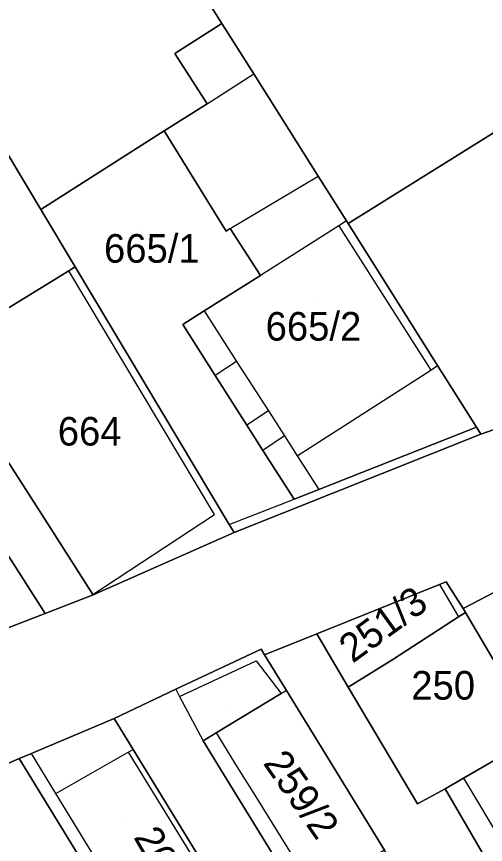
# Model space of a CAD drawing. Extents: x -263943 to -261149, y -1236934 to -1230686.
# Drawn here: x -262505 to -262472.2, y -1235556.7 to -1235498.8 of the extents above; entities that cross this region are included whole.
import ezdxf

# ---------------------------------------------------------------- set-up
doc = ezdxf.new("R2010")
doc.units = 0
for name, color, linetype in [('body_kn', 7, 'Continuous'), ('kladpar_druhypozemkov', 7, 'Continuous'), ('kladpar_hranice', 7, 'Continuous'), ('kladpar_parcelnecisla', 7, 'Continuous'), ('kladpar_plochy', 7, 'Continuous'), ('zappar_hrandruhpozemk', 7, 'Continuous')]:
    doc.layers.add(name, color=color, linetype=linetype)

msp = doc.modelspace()

# ---------------------------------------------------------------- linework, layer by layer
at = {"layer": 'body_kn'}
for p, q in [((-262490.64, -1235499.3), (-262490.64, -1235499.3)), ((-262490.64, -1235499.3), (-262490.64, -1235499.3)), ((-262493.93, -1235501.39), (-262493.93, -1235501.39)), ((-262488.41, -1235502.83), (-262488.41, -1235502.83)), ((-262491.68, -1235504.91), (-262491.68, -1235504.91)), ((-262491.68, -1235504.91), (-262491.68, -1235504.91)), ((-262494.68, -1235506.81), (-262494.68, -1235506.81)), ((-262494.68, -1235506.81), (-262494.68, -1235506.81)), ((-262483.9, -1235509.98), (-262483.9, -1235509.98)), ((-262503.31, -1235512.3), (-262503.31, -1235512.3)), ((-262481.93, -1235513.11), (-262481.93, -1235513.11)), ((-262481.93, -1235513.11), (-262481.93, -1235513.11)), ((-262490.05, -1235513.65), (-262490.05, -1235513.65)), ((-262490.05, -1235513.65), (-262490.05, -1235513.65)), ((-262482.47, -1235513.45), (-262482.47, -1235513.45)), ((-262481.81, -1235513.3), (-262481.81, -1235513.3)), ((-262490.35, -1235513.83), (-262490.35, -1235513.83)), ((-262501.34, -1235516.6), (-262501.34, -1235516.6)), ((-262501.34, -1235516.6), (-262501.34, -1235516.6)), ((-262500.9, -1235516.33), (-262500.9, -1235516.33)), ((-262487.95, -1235516.92), (-262487.95, -1235516.92)), ((-262487.95, -1235516.92), (-262487.95, -1235516.92)), ((-262491.88, -1235519.4), (-262491.88, -1235519.4)), ((-262491.88, -1235519.4), (-262491.88, -1235519.4)), ((-262493.38, -1235520.35), (-262493.38, -1235520.35)), ((-262489.61, -1235522.94), (-262489.61, -1235522.94)), ((-262489.61, -1235522.94), (-262489.61, -1235522.94)), ((-262476.03, -1235523.54), (-262476.03, -1235523.54)), ((-262476.03, -1235523.54), (-262476.03, -1235523.54)), ((-262475.55, -1235523.23), (-262475.55, -1235523.23)), ((-262491.11, -1235523.92), (-262491.11, -1235523.92)), ((-262487.39, -1235526.4), (-262487.39, -1235526.4)), ((-262487.39, -1235526.4), (-262487.39, -1235526.4)), ((-262488.9, -1235527.39), (-262488.9, -1235527.39)), ((-262472.84, -1235527.54), (-262472.84, -1235527.54)), ((-262486.27, -1235528.14), (-262486.27, -1235528.14)), ((-262486.27, -1235528.14), (-262486.27, -1235528.14)), ((-262472.53, -1235528.03), (-262472.53, -1235528.03)), ((-262487.77, -1235529.17), (-262487.77, -1235529.17)), ((-262485.38, -1235529.53), (-262485.38, -1235529.53)), ((-262483.86, -1235531.89), (-262483.86, -1235531.89)), ((-262485.59, -1235532.57), (-262485.59, -1235532.57)), ((-262491.15, -1235533.64), (-262491.15, -1235533.64)), ((-262491.15, -1235533.64), (-262491.15, -1235533.64)), ((-262490.12, -1235534.35), (-262490.12, -1235534.35)), ((-262490.12, -1235534.35), (-262490.12, -1235534.35)), ((-262502.5, -1235534.82), (-262502.5, -1235534.82)), ((-262489.79, -1235534.91), (-262489.79, -1235534.91)), ((-262489.79, -1235534.91), (-262489.79, -1235534.91)), ((-262475.43, -1235538.55), (-262475.43, -1235538.55)), ((-262475.43, -1235538.55), (-262475.43, -1235538.55)), ((-262474.96, -1235538.36), (-262474.96, -1235538.36)), ((-262499.67, -1235539.23), (-262499.67, -1235539.23)), ((-262499.67, -1235539.23), (-262499.67, -1235539.23)), ((-262499.64, -1235539.27), (-262499.64, -1235539.27)), ((-262473.77, -1235540.22), (-262473.77, -1235540.22)), ((-262502.99, -1235540.57), (-262502.99, -1235540.57)), ((-262502.99, -1235540.57), (-262502.99, -1235540.57)), ((-262474.08, -1235540.8), (-262474.08, -1235540.8)), ((-262473.61, -1235540.5), (-262473.61, -1235540.5)), ((-262483.99, -1235541.99), (-262483.99, -1235541.99)), ((-262487.9, -1235543.07), (-262487.9, -1235543.07)), ((-262487.9, -1235543.07), (-262487.9, -1235543.07)), ((-262488.25, -1235543.88), (-262488.25, -1235543.88)), ((-262487.66, -1235543.46), (-262487.66, -1235543.46)), ((-262487.66, -1235543.46), (-262487.66, -1235543.46)), ((-262478.68, -1235543.78), (-262478.68, -1235543.78)), ((-262493.86, -1235545.87), (-262493.86, -1235545.87)), ((-262493.86, -1235545.87), (-262493.86, -1235545.87)), ((-262486.49, -1235546.17), (-262486.49, -1235546.17)), ((-262486.13, -1235545.95), (-262486.13, -1235545.95)), ((-262481.81, -1235545.71), (-262481.81, -1235545.71)), ((-262481.81, -1235545.71), (-262481.81, -1235545.71)), ((-262493.6, -1235546.37), (-262493.6, -1235546.37)), ((-262498.17, -1235547.9), (-262498.17, -1235547.9)), ((-262491.04, -1235548.92), (-262491.04, -1235548.92)), ((-262491.04, -1235548.92), (-262491.04, -1235548.92)), ((-262491.96, -1235549.48), (-262491.96, -1235549.48)), ((-262503.46, -1235550.14), (-262503.46, -1235550.14)), ((-262496.84, -1235550.07), (-262496.84, -1235550.07)), ((-262504.81, -1235550.72), (-262504.81, -1235550.72)), ((-262503.96, -1235550.36), (-262503.96, -1235550.36)), ((-262497.19, -1235550.27), (-262497.19, -1235550.27)), ((-262489.56, -1235551.31), (-262489.56, -1235551.31)), ((-262490.49, -1235551.87), (-262490.49, -1235551.87)), ((-262473.74, -1235552.08), (-262473.74, -1235552.08)), ((-262473.74, -1235552.08), (-262473.74, -1235552.08)), ((-262488.46, -1235553.09), (-262488.46, -1235553.09)), ((-262475.03, -1235552.83), (-262475.03, -1235552.83)), ((-262502.25, -1235553.16), (-262502.25, -1235553.16)), ((-262489.37, -1235553.69), (-262489.37, -1235553.69)), ((-262476.95, -1235553.89), (-262476.95, -1235553.89))]:
    msp.add_line(p, q, dxfattribs=at)
at = {"layer": 'kladpar_druhypozemkov'}
for p, q in [((-262496.1, -1235513.63), (-262496.1, -1235513.63)), ((-262483.9, -1235518.63), (-262483.9, -1235518.63)), ((-262499.51, -1235526.83), (-262499.51, -1235526.83)), ((-262482.19, -1235543), (-262482.19, -1235543)), ((-262475.14, -1235544.52), (-262475.14, -1235544.52)), ((-262490.12, -1235547.37), (-262490.12, -1235547.37)), ((-262483.86, -1235552.94), (-262483.86, -1235552.94)), ((-262497.65, -1235555.24), (-262497.65, -1235555.24))]:
    msp.add_line(p, q, dxfattribs=at)
at = {"layer": 'kladpar_hranice'}
for points in [[(-262490.64, -1235499.3), (-262493.93, -1235501.39), (-262491.68, -1235504.91), (-262494.68, -1235506.81), (-262503.31, -1235512.3), (-262518.04, -1235487.66), (-262527.31, -1235472.16), (-262527.63, -1235471.62), (-262522.3, -1235468.31), (-262520.69, -1235467.38), (-262516.77, -1235473.71), (-262509.58, -1235469.21), (-262500.08, -1235484.3), (-262496.68, -1235489.7), (-262490.64, -1235499.3)], [(-262466.56, -1235503.77), (-262481.81, -1235513.3), (-262481.93, -1235513.11), (-262483.9, -1235509.98), (-262488.41, -1235502.83), (-262490.64, -1235499.3), (-262496.68, -1235489.7), (-262500.08, -1235484.3), (-262484.57, -1235474.74), (-262483.69, -1235476.16), (-262481.31, -1235480), (-262466.56, -1235503.77)], [(-262501.34, -1235516.6), (-262508.81, -1235521.16), (-262510.44, -1235522.15), (-262507.57, -1235526.91), (-262502.5, -1235534.82), (-262499.67, -1235539.23), (-262499.64, -1235539.27), (-262502.99, -1235540.57), (-262505.55, -1235536.58), (-262512.71, -1235525.4), (-262515.62, -1235520.86), (-262531.67, -1235496), (-262518.04, -1235487.66), (-262503.31, -1235512.3), (-262500.9, -1235516.33), (-262501.34, -1235516.6)], [(-262494.68, -1235506.81), (-262491.68, -1235504.91), (-262493.93, -1235501.39), (-262490.64, -1235499.3), (-262488.41, -1235502.83), (-262483.9, -1235509.98), (-262481.93, -1235513.11), (-262481.81, -1235513.3), (-262475.55, -1235523.23), (-262472.84, -1235527.54), (-262483.86, -1235531.89), (-262485.59, -1235532.57), (-262487.77, -1235529.17), (-262488.9, -1235527.39), (-262491.11, -1235523.92), (-262493.38, -1235520.35), (-262491.88, -1235519.4), (-262487.95, -1235516.92), (-262490.05, -1235513.65), (-262490.35, -1235513.83), (-262494.68, -1235506.81)], [(-262455.26, -1235521.99), (-262472.53, -1235528.03), (-262472.84, -1235527.54), (-262475.55, -1235523.23), (-262481.81, -1235513.3), (-262466.56, -1235503.77), (-262464.13, -1235507.7), (-262458.39, -1235516.94), (-262455.26, -1235521.99)], [(-262487.95, -1235516.92), (-262491.88, -1235519.4), (-262493.38, -1235520.35), (-262491.11, -1235523.92), (-262488.9, -1235527.39), (-262487.77, -1235529.17), (-262485.59, -1235532.57), (-262483.86, -1235531.89), (-262472.84, -1235527.54), (-262472.53, -1235528.03), (-262489.79, -1235534.91), (-262490.12, -1235534.35), (-262500.9, -1235516.33), (-262503.31, -1235512.3), (-262494.68, -1235506.81), (-262490.35, -1235513.83), (-262490.05, -1235513.65), (-262487.95, -1235516.92)], [(-262489.79, -1235534.91), (-262499.64, -1235539.27), (-262499.67, -1235539.23), (-262502.5, -1235534.82), (-262507.57, -1235526.91), (-262510.44, -1235522.15), (-262508.81, -1235521.16), (-262501.34, -1235516.6), (-262500.9, -1235516.33), (-262490.12, -1235534.35), (-262489.79, -1235534.91)], [(-262537.37, -1235554.74), (-262532.87, -1235552.78), (-262531.41, -1235552.15), (-262528.83, -1235551.02), (-262528.46, -1235550.85), (-262523.8, -1235548.78), (-262520.14, -1235547.14), (-262517.89, -1235546.28), (-262517.35, -1235546.07), (-262514.25, -1235544.89), (-262512.5, -1235544.22), (-262502.99, -1235540.57), (-262499.64, -1235539.27), (-262489.79, -1235534.91), (-262472.53, -1235528.03), (-262455.26, -1235521.99), (-262451.3, -1235520.8), (-262450.59, -1235520.59), (-262444.65, -1235518.81), (-262444.17, -1235518.67)], [(-262502.99, -1235540.57), (-262512.5, -1235544.22), (-262514.25, -1235544.89), (-262517.35, -1235546.07), (-262517.89, -1235546.28), (-262520.14, -1235547.14), (-262521.94, -1235544.32), (-262524.93, -1235539.64), (-262526.89, -1235536.56), (-262530.83, -1235530.38), (-262531.04, -1235530.05), (-262528.57, -1235528.58), (-262515.62, -1235520.86), (-262512.71, -1235525.4), (-262505.55, -1235536.58), (-262502.99, -1235540.57)], [(-262441.86, -1235527.77), (-262449.95, -1235530.54), (-262450.38, -1235530.69), (-262459.13, -1235533.68), (-262460.06, -1235533.09), (-262473.77, -1235540.22), (-262474.96, -1235538.36), (-262475.43, -1235538.55), (-262483.99, -1235541.99), (-262487.66, -1235543.46), (-262487.9, -1235543.07), (-262493.86, -1235545.87), (-262498.17, -1235547.9), (-262503.46, -1235550.14), (-262503.96, -1235550.36), (-262504.81, -1235550.72), (-262509.2, -1235552.61), (-262515.67, -1235555.39), (-262516.86, -1235555.72), (-262521.02, -1235557.42)], [(-262448.9, -1235550.42), (-262455.19, -1235553.66), (-262446.22, -1235568.5), (-262451.11, -1235571.48), (-262453.92, -1235573.19), (-262454.26, -1235573.4), (-262454.89, -1235572.37), (-262457.87, -1235567.12), (-262461.12, -1235561.62), (-262468.54, -1235549.07), (-262473.61, -1235540.5), (-262473.77, -1235540.22), (-262460.06, -1235533.09), (-262459.13, -1235533.68), (-262458.31, -1235535.02), (-262452.44, -1235544.63), (-262448.9, -1235550.42)], [(-262475.43, -1235538.55), (-262474.96, -1235538.36), (-262473.77, -1235540.22), (-262473.61, -1235540.5), (-262474.08, -1235540.8), (-262478.68, -1235543.78), (-262481.81, -1235545.71), (-262483.99, -1235541.99), (-262475.43, -1235538.55)], [(-262481.81, -1235545.71), (-262478.68, -1235543.78), (-262474.08, -1235540.8), (-262473.61, -1235540.5), (-262468.54, -1235549.07), (-262468.98, -1235549.33), (-262473.74, -1235552.08), (-262475.03, -1235552.83), (-262476.95, -1235553.89), (-262481.81, -1235545.71)], [(-262487.66, -1235543.46), (-262483.99, -1235541.99), (-262481.81, -1235545.71), (-262476.95, -1235553.89), (-262475.03, -1235552.83), (-262467.68, -1235565.47), (-262469.64, -1235566.59), (-262463.02, -1235577.36), (-262464.32, -1235578.16), (-262465.86, -1235579.1), (-262468.89, -1235574.07), (-262468.94, -1235573.99), (-262470.33, -1235571.69), (-262471.84, -1235569.18), (-262479.26, -1235557.12), (-262486.13, -1235545.95), (-262487.66, -1235543.46)], [(-262490.21, -1235560.91), (-262496.84, -1235550.07), (-262498.17, -1235547.9), (-262493.86, -1235545.87), (-262487.9, -1235543.07)], [(-262487.9, -1235543.07), (-262487.66, -1235543.46), (-262486.13, -1235545.95), (-262486.49, -1235546.17), (-262491.04, -1235548.92), (-262491.96, -1235549.48), (-262490.49, -1235551.87), (-262489.37, -1235553.69), (-262485.11, -1235560.59)], [(-262479.26, -1235557.12), (-262484.16, -1235560.02), (-262485.11, -1235560.59), (-262489.37, -1235553.69), (-262490.49, -1235551.87), (-262491.96, -1235549.48), (-262491.04, -1235548.92), (-262486.49, -1235546.17), (-262486.13, -1235545.95), (-262479.26, -1235557.12)], [(-262496.27, -1235564.68), (-262504.81, -1235550.72), (-262503.96, -1235550.36), (-262503.46, -1235550.14), (-262498.17, -1235547.9), (-262496.84, -1235550.07), (-262490.21, -1235560.91), (-262490.53, -1235561.11), (-262495.5, -1235564.2), (-262496.27, -1235564.68)], [(-262461.5, -1235561.84), (-262466.27, -1235564.64), (-262467.68, -1235565.47), (-262475.03, -1235552.83), (-262473.74, -1235552.08), (-262468.98, -1235549.33), (-262468.54, -1235549.07), (-262461.12, -1235561.62), (-262461.5, -1235561.84)], [(-262485.79, -1235585.63), (-262488.5, -1235587.3), (-262493.08, -1235579.87), (-262494.64, -1235577.23), (-262508.17, -1235554.35), (-262509.2, -1235552.61), (-262504.81, -1235550.72), (-262496.27, -1235564.68), (-262490.09, -1235574.79), (-262487.31, -1235579.33), (-262484.1, -1235584.59)]]:
    msp.add_lwpolyline(points, dxfattribs=at)
at = {"layer": 'kladpar_plochy'}
for p, q in [((-262509.2, -1235552.61), (-262504.81, -1235550.72)), ((-262504.81, -1235550.72), (-262496.27, -1235564.68))]:
    msp.add_line(p, q, dxfattribs=at)
for points in [[(-262490.64, -1235499.3), (-262493.93, -1235501.39), (-262491.68, -1235504.91), (-262494.68, -1235506.81), (-262503.31, -1235512.3), (-262518.04, -1235487.66), (-262527.31, -1235472.16), (-262527.63, -1235471.62), (-262522.3, -1235468.31), (-262520.69, -1235467.38), (-262516.77, -1235473.71), (-262509.58, -1235469.21), (-262500.08, -1235484.3), (-262496.68, -1235489.7)], [(-262466.56, -1235503.77), (-262481.81, -1235513.3), (-262481.93, -1235513.11), (-262483.9, -1235509.98), (-262488.41, -1235502.83), (-262490.64, -1235499.3), (-262496.68, -1235489.7), (-262500.08, -1235484.3), (-262484.57, -1235474.74), (-262483.69, -1235476.16), (-262481.31, -1235480)], [(-262501.34, -1235516.6), (-262508.81, -1235521.16), (-262510.44, -1235522.15), (-262507.57, -1235526.91), (-262502.5, -1235534.82), (-262499.67, -1235539.23), (-262499.64, -1235539.27), (-262502.99, -1235540.57), (-262505.55, -1235536.58), (-262512.71, -1235525.4), (-262515.62, -1235520.86), (-262531.67, -1235496), (-262518.04, -1235487.66), (-262503.31, -1235512.3), (-262500.9, -1235516.33)], [(-262494.68, -1235506.81), (-262491.68, -1235504.91), (-262493.93, -1235501.39), (-262490.64, -1235499.3), (-262488.41, -1235502.83), (-262483.9, -1235509.98), (-262481.93, -1235513.11), (-262481.81, -1235513.3), (-262475.55, -1235523.23), (-262472.84, -1235527.54), (-262483.86, -1235531.89), (-262485.59, -1235532.57), (-262487.77, -1235529.17), (-262488.9, -1235527.39), (-262491.11, -1235523.92), (-262493.38, -1235520.35), (-262491.88, -1235519.4), (-262487.95, -1235516.92), (-262490.05, -1235513.65), (-262490.35, -1235513.83)], [(-262455.26, -1235521.99), (-262472.53, -1235528.03), (-262472.84, -1235527.54), (-262475.55, -1235523.23), (-262481.81, -1235513.3), (-262466.56, -1235503.77), (-262464.13, -1235507.7), (-262458.39, -1235516.94)], [(-262487.95, -1235516.92), (-262491.88, -1235519.4), (-262493.38, -1235520.35), (-262491.11, -1235523.92), (-262488.9, -1235527.39), (-262487.77, -1235529.17), (-262485.59, -1235532.57), (-262483.86, -1235531.89), (-262472.84, -1235527.54), (-262472.53, -1235528.03), (-262489.79, -1235534.91), (-262490.12, -1235534.35), (-262500.9, -1235516.33), (-262503.31, -1235512.3), (-262494.68, -1235506.81), (-262490.35, -1235513.83), (-262490.05, -1235513.65)], [(-262489.79, -1235534.91), (-262499.64, -1235539.27), (-262499.67, -1235539.23), (-262502.5, -1235534.82), (-262507.57, -1235526.91), (-262510.44, -1235522.15), (-262508.81, -1235521.16), (-262501.34, -1235516.6), (-262500.9, -1235516.33), (-262490.12, -1235534.35)], [(-262502.99, -1235540.57), (-262512.5, -1235544.22), (-262514.25, -1235544.89), (-262517.35, -1235546.07), (-262517.89, -1235546.28), (-262520.14, -1235547.14), (-262521.94, -1235544.32), (-262524.93, -1235539.64), (-262526.89, -1235536.56), (-262530.83, -1235530.38), (-262531.04, -1235530.05), (-262528.57, -1235528.58), (-262515.62, -1235520.86), (-262512.71, -1235525.4), (-262505.55, -1235536.58)], [(-262448.9, -1235550.42), (-262455.19, -1235553.66), (-262446.22, -1235568.5), (-262451.11, -1235571.48), (-262453.92, -1235573.19), (-262454.26, -1235573.4), (-262454.89, -1235572.37), (-262457.87, -1235567.12), (-262461.12, -1235561.62), (-262468.54, -1235549.07), (-262473.61, -1235540.5), (-262473.77, -1235540.22), (-262460.06, -1235533.09), (-262459.13, -1235533.68), (-262458.31, -1235535.02), (-262452.44, -1235544.63)], [(-262475.43, -1235538.55), (-262474.96, -1235538.36), (-262473.77, -1235540.22), (-262473.61, -1235540.5), (-262474.08, -1235540.8), (-262478.68, -1235543.78), (-262481.81, -1235545.71), (-262483.99, -1235541.99)], [(-262481.81, -1235545.71), (-262478.68, -1235543.78), (-262474.08, -1235540.8), (-262473.61, -1235540.5), (-262468.54, -1235549.07), (-262468.98, -1235549.33), (-262473.74, -1235552.08), (-262475.03, -1235552.83), (-262476.95, -1235553.89)], [(-262487.66, -1235543.46), (-262483.99, -1235541.99), (-262481.81, -1235545.71), (-262476.95, -1235553.89), (-262475.03, -1235552.83), (-262467.68, -1235565.47), (-262469.64, -1235566.59), (-262463.02, -1235577.36), (-262464.32, -1235578.16), (-262465.86, -1235579.1), (-262468.89, -1235574.07), (-262468.94, -1235573.99), (-262470.33, -1235571.69), (-262471.84, -1235569.18), (-262479.26, -1235557.12), (-262486.13, -1235545.95)], [(-262479.26, -1235557.12), (-262484.16, -1235560.02), (-262485.11, -1235560.59), (-262489.37, -1235553.69), (-262490.49, -1235551.87), (-262491.96, -1235549.48), (-262491.04, -1235548.92), (-262486.49, -1235546.17), (-262486.13, -1235545.95)], [(-262496.27, -1235564.68), (-262504.81, -1235550.72), (-262503.96, -1235550.36), (-262503.46, -1235550.14), (-262498.17, -1235547.9), (-262496.84, -1235550.07), (-262490.21, -1235560.91), (-262490.53, -1235561.11), (-262495.5, -1235564.2)], [(-262461.5, -1235561.84), (-262466.27, -1235564.64), (-262467.68, -1235565.47), (-262475.03, -1235552.83), (-262473.74, -1235552.08), (-262468.98, -1235549.33), (-262468.54, -1235549.07), (-262461.12, -1235561.62)]]:
    msp.add_lwpolyline(points, close=True, dxfattribs=at)
for points in [[(-262537.37, -1235554.74), (-262532.87, -1235552.78), (-262531.41, -1235552.15), (-262528.83, -1235551.02), (-262528.46, -1235550.85), (-262523.8, -1235548.78), (-262520.14, -1235547.14), (-262517.89, -1235546.28), (-262517.35, -1235546.07), (-262514.25, -1235544.89), (-262512.5, -1235544.22), (-262502.99, -1235540.57), (-262499.64, -1235539.27), (-262489.79, -1235534.91), (-262472.53, -1235528.03), (-262455.26, -1235521.99), (-262451.3, -1235520.8), (-262450.59, -1235520.59), (-262444.65, -1235518.81), (-262444.17, -1235518.67)], [(-262441.86, -1235527.77), (-262449.95, -1235530.54), (-262450.38, -1235530.69), (-262459.13, -1235533.68), (-262460.06, -1235533.09), (-262473.77, -1235540.22), (-262474.96, -1235538.36), (-262475.43, -1235538.55), (-262483.99, -1235541.99), (-262487.66, -1235543.46), (-262487.9, -1235543.07), (-262493.86, -1235545.87), (-262498.17, -1235547.9), (-262503.46, -1235550.14), (-262503.96, -1235550.36), (-262504.81, -1235550.72), (-262509.2, -1235552.61), (-262515.67, -1235555.39), (-262516.86, -1235555.72), (-262521.02, -1235557.42)], [(-262490.21, -1235560.91), (-262496.84, -1235550.07), (-262498.17, -1235547.9), (-262493.86, -1235545.87), (-262487.9, -1235543.07), (-262487.66, -1235543.46), (-262486.13, -1235545.95), (-262486.49, -1235546.17), (-262491.04, -1235548.92), (-262491.96, -1235549.48), (-262490.49, -1235551.87), (-262489.37, -1235553.69), (-262485.11, -1235560.59)]]:
    msp.add_lwpolyline(points, dxfattribs=at)
at = {"layer": 'zappar_hrandruhpozemk'}
for p, q in [((-262491.68, -1235504.91), (-262488.41, -1235502.83)), ((-262490.05, -1235513.65), (-262483.9, -1235509.98)), ((-262481.93, -1235513.11), (-262482.47, -1235513.45)), ((-262482.47, -1235513.45), (-262487.95, -1235516.92)), ((-262482.47, -1235513.45), (-262476.03, -1235523.54)), ((-262491.15, -1235533.64), (-262501.34, -1235516.6)), ((-262489.61, -1235522.94), (-262491.11, -1235523.92)), ((-262485.38, -1235529.53), (-262476.03, -1235523.54)), ((-262476.03, -1235523.54), (-262475.55, -1235523.23)), ((-262487.39, -1235526.4), (-262488.9, -1235527.39)), ((-262486.27, -1235528.14), (-262487.77, -1235529.17)), ((-262485.38, -1235529.53), (-262483.86, -1235531.89)), ((-262490.12, -1235534.35), (-262485.59, -1235532.57)), ((-262499.67, -1235539.23), (-262491.15, -1235533.64)), ((-262475.43, -1235538.55), (-262474.08, -1235540.8)), ((-262493.6, -1235546.37), (-262488.25, -1235543.88)), ((-262488.25, -1235543.88), (-262486.49, -1235546.17)), ((-262493.86, -1235545.87), (-262493.6, -1235546.37)), ((-262493.6, -1235546.37), (-262491.96, -1235549.48)), ((-262497.19, -1235550.27), (-262496.84, -1235550.07)), ((-262502.25, -1235553.16), (-262503.96, -1235550.36)), ((-262502.25, -1235553.16), (-262497.19, -1235550.27)), ((-262497.19, -1235550.27), (-262490.53, -1235561.11)), ((-262473.74, -1235552.08), (-262466.27, -1235564.64)), ((-262495.5, -1235564.2), (-262502.25, -1235553.16))]:
    msp.add_line(p, q, dxfattribs=at)
for points in [[(-262491.88, -1235519.4), (-262489.61, -1235522.94), (-262487.39, -1235526.4), (-262486.27, -1235528.14), (-262485.38, -1235529.53)], [(-262491.04, -1235548.92), (-262489.56, -1235551.31), (-262488.46, -1235553.09), (-262484.16, -1235560.02)]]:
    msp.add_lwpolyline(points, dxfattribs=at)

# ---------------------------------------------------------------- texts
at = {"layer": 'kladpar_parcelnecisla'}
for s, p in [('665/1', (-262498.885, -1235516.03)), ('665/2', (-262487.581, -1235521.48)), ('664', (-262502.119, -1235528.82)), ('250', (-262477.392, -1235546.59))]:
    msp.add_text(s, height=2, dxfattribs=at).set_placement(p)
for s, rotation, p in [('251/3', 36, (-262481.496, -1235544.086)), ('259/2', 305, (-262487.807, -1235551.038)), ('260', 300, (-262496.855, -1235556.207))]:
    msp.add_text(s, height=2, rotation=rotation, dxfattribs=at).set_placement(p)

doc.saveas('drawing.dxf')
